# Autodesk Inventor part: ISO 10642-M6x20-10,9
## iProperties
Shininess: 64.0
Length Units: 11269
Angle Units: 11279
Time Units: 11290
Mass Units: 11283
Length Display Precision: 3
Angle Display Precision: 2
Compacted: True
Part Number: ISO 10642-M6x20-10,9
Document SubType Name: Modeling
Created: 2005-02
Material: Par défaut
Designer: LEGERET Philippe
Catalog Web Link: www.traceparts.com
Description: Vis à métaux - Tête fraisée à 6 pans creux ISO 10642 - M6x20-10,9
Density: 0.0
Volumn: 0.0
Area: 0.0
PropertySet Name: Model Information
Control State: 0
Master: False
Checked Out: False
Author: Trace Parts S.A.
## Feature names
1. Base1
